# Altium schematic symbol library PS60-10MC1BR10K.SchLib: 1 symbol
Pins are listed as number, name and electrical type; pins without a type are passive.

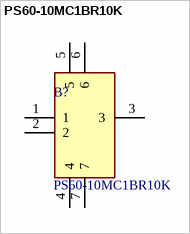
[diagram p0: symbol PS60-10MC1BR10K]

## PS60-10MC1BR10K
designator B?
Slide Potentiometers 10K ohm 20% 60mm Slide Potentiometer; Manufacturer_Name: TT Electronics; Geometry.Height: 15mm
footprint PS6010MC1BR10K
pins: 1, 2, 3, 4, 5, 6, 7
